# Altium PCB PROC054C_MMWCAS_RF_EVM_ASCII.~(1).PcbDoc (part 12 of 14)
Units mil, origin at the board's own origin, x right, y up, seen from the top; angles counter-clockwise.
Board outline 6299.21 x 5370.07 mil, 8 copper layers (L1 TOP, L2 GND, L3 SIGNAL 1, L4 GND, L5 SIGNAL 2, L6 SIGNAL 3, L7 GND, L8 BOTTOM), stack 53.5 mil thick; 775 components, 552 nets, 2648 pads, 7845 vias.
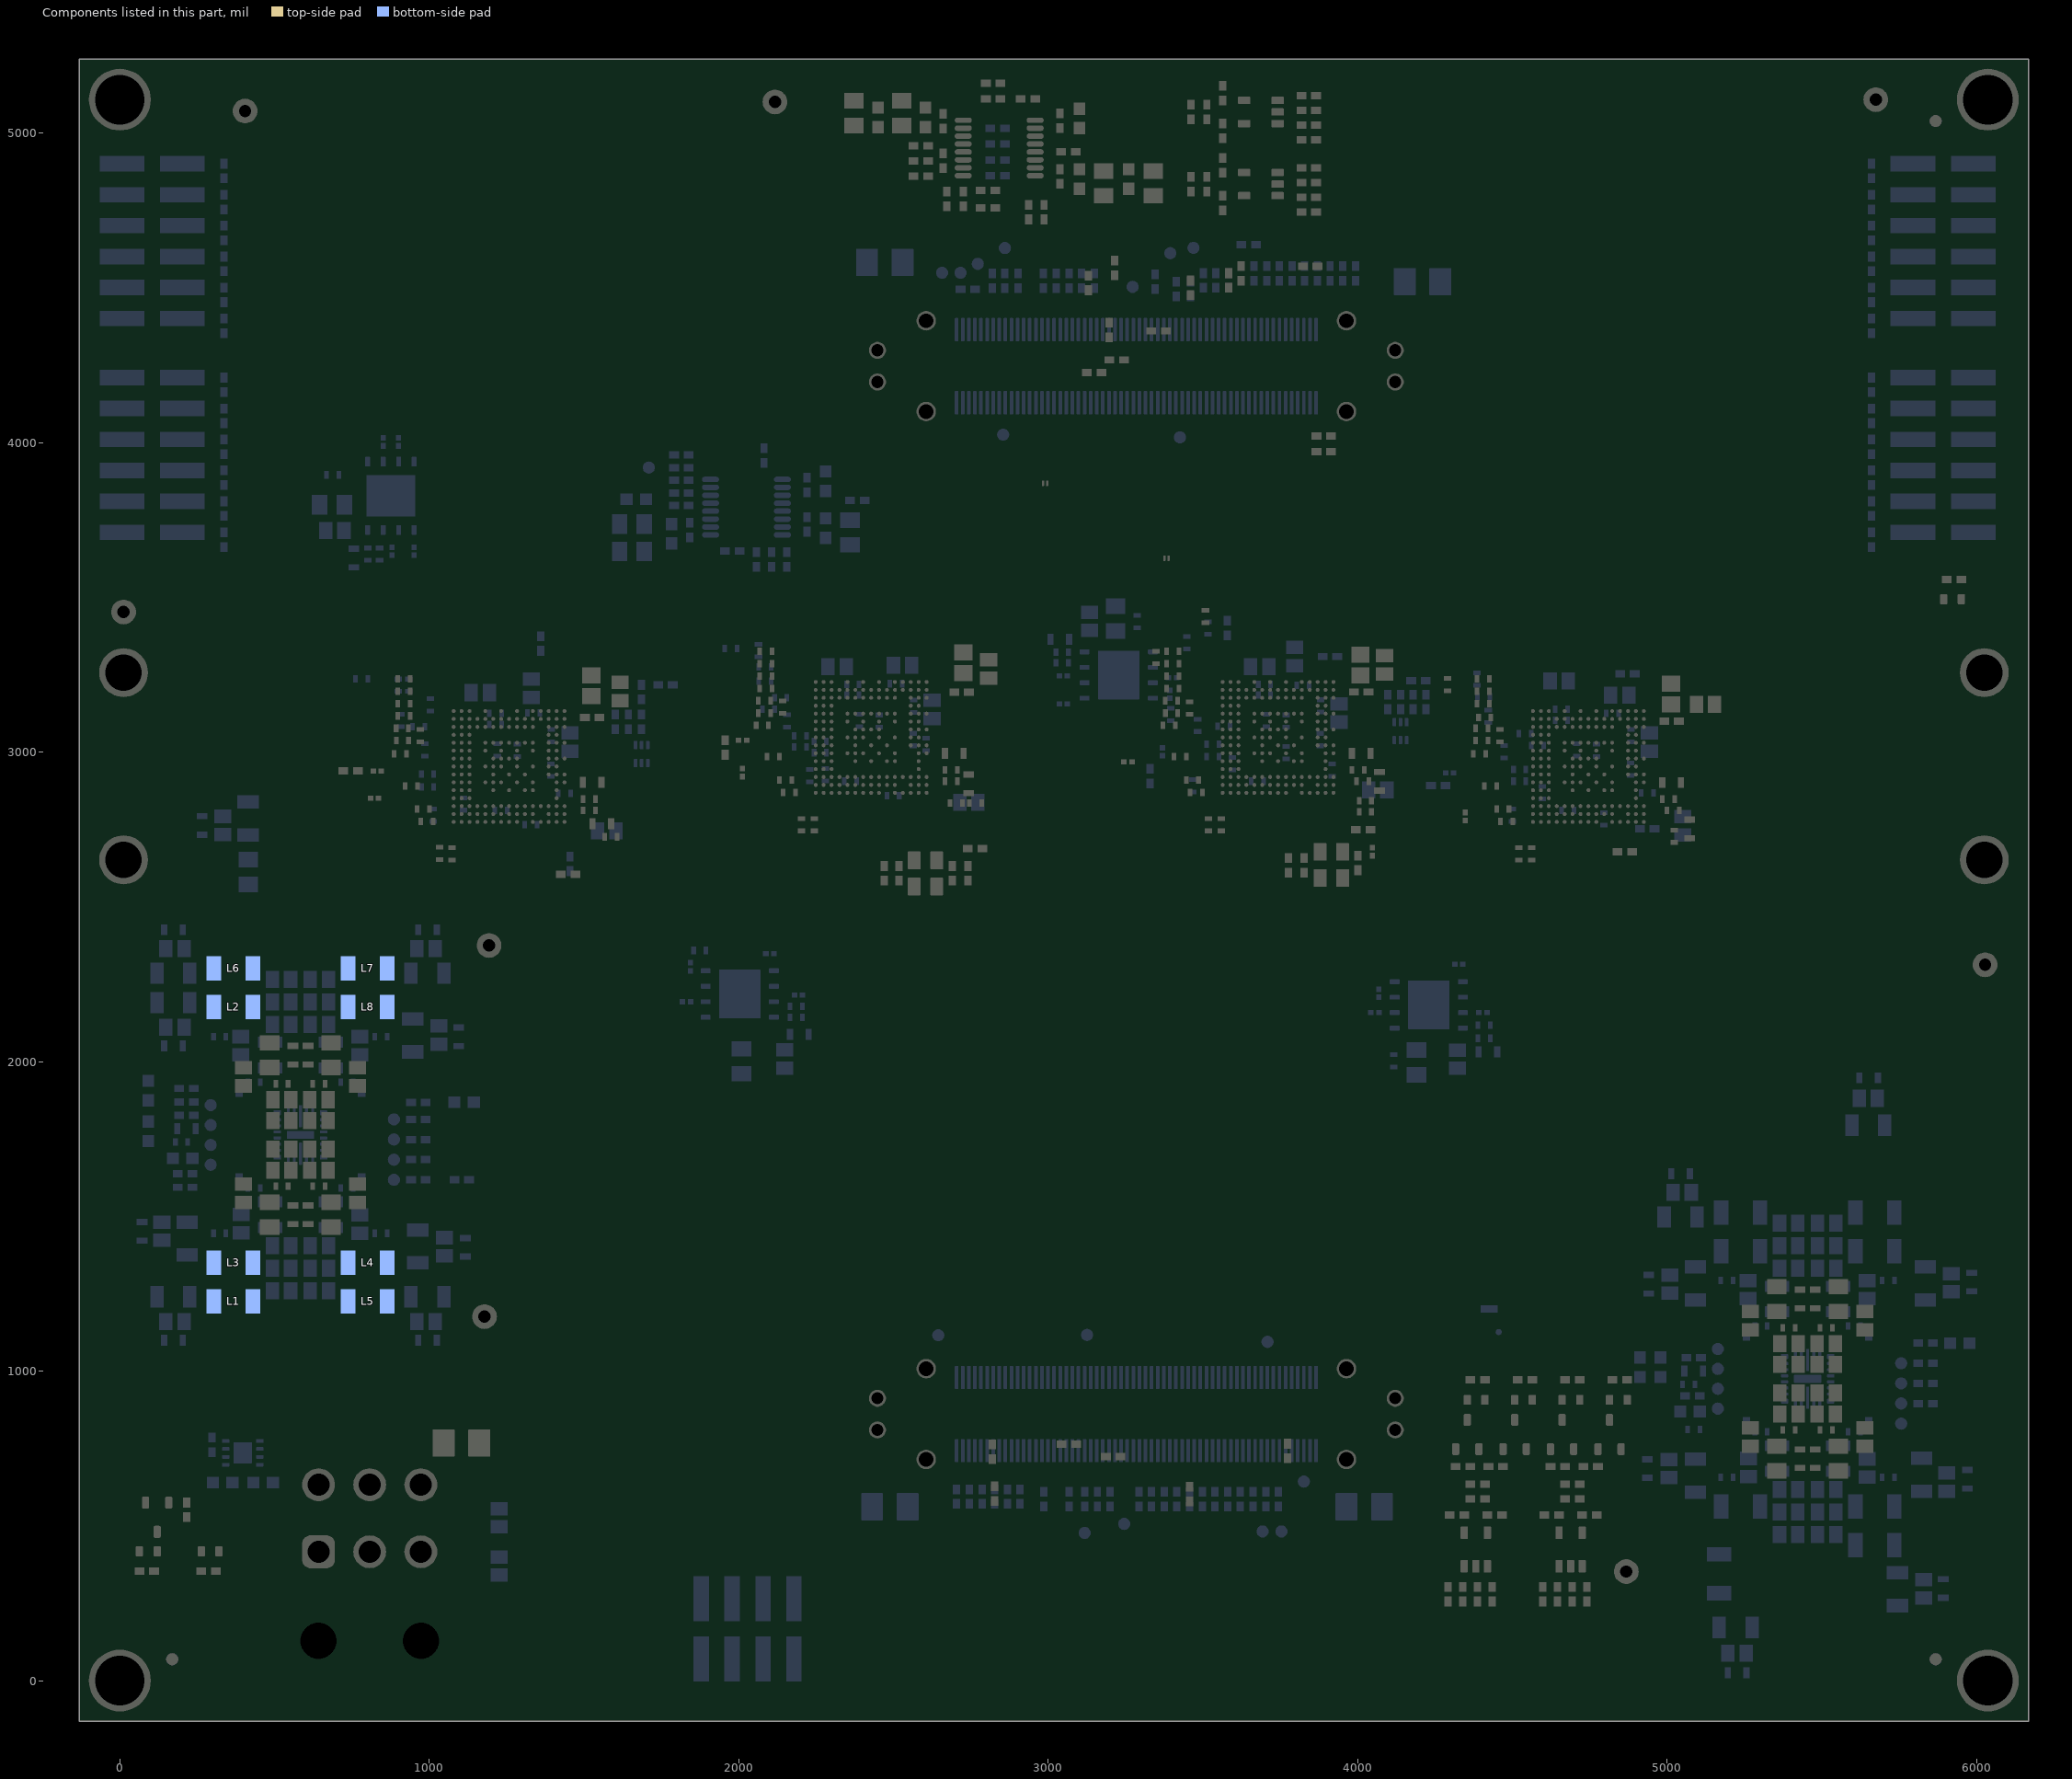
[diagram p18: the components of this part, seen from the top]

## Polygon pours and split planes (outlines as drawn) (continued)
GND on L8 BOTTOM "L8_BOTTOM_GND_P29719" (solid, remove dead copper, pour order 29719): 17 vertices, not listed, extent 731.81,1863.73 842.14,2042.6
GND on L8 BOTTOM "L8_BOTTOM_GND_P29760" (solid, remove dead copper, pour order 29760): 24 vertices, not listed, extent 530.59,1923.28 636.24,2303.75
12XX_4_1V0_RF1_FILT on L8 BOTTOM "L8_BOTTOM_12XX_4_1V0_RF1_FILT_P29792" (solid, remove dead copper, pour order 29792): 24 vertices, not listed, extent 479.15,2247.44 1317.72,3551.66
12XX_4_1V2_FILT on L8 BOTTOM "L8_BOTTOM_12XX_4_1V2_FILT_P29790" (solid, remove dead copper, pour order 29790): 19 vertices, not listed, extent -131.11,1296.94 332.13,3060.36
12XX_4_1V8_FILT on L8 BOTTOM "L8_BOTTOM_12XX_4_1V8_FILT_P29702" (solid, remove dead copper, pour order 29702): 1314.48,3068.75 1283.95,3099.27 1283.95,3185.88 1297.79,3199.72 1357.07,3199.72 1360.98,3195.82 1360.98,3156.42 1356.01,3151.45 1340.03,3151.45 1328.67,3140.09 1328.67,3082.94 1316.61,3070.88
12XX_3_1V8_FILT on L8 BOTTOM "L8_BOTTOM_12XX_3_1V8_FILT_P29703" (solid, remove dead copper, pour order 29703): 3799.3,3157.94 3799.3,3160.31 3764.59,3195.02 3764.59,3296.99 3768.63,3301.03 3817.76,3301.03 3824.31,3294.48 3824.31,3174.4 3808.57,3158.65
LMK2_3V3 on L8 BOTTOM "L8_BOTTOM_LMK2_3V3_P29704" (solid, remove dead copper, pour order 29704): 1985.94,3661.24 2019.56,3661.24 2021.37,3659.44 2021.37,3627.32 2032.47,3616.21 2066.39,3616.21 2070.9,3611.71 2070.9,3549.27 2068.19,3546.56 2002.15,3546.56 1982.34,3566.38 1982.34,3657.85 1985.51,3661.02
PMIC1_SW_B1 on L8 BOTTOM "L8_BOTTOM_PMIC1_SW_B1_P29708" (solid, remove dead copper, pour order 29708): 564.74,1621.53 540.48,1597.27 540.48,1534.8 531.2,1525.51 446.86,1525.51 441.43,1530.95 441.43,1600.06 444.98,1603.62 526.25,1603.62 564.74,1642.11
PMIC2_SW_B3 on L8 BOTTOM "L8_BOTTOM_PMIC2_SW_B3_P29711" (solid, remove dead copper, pour order 29711): 5435.47,1116.54 5411.21,1140.8 5411.21,1203.27 5401.92,1212.56 5317.59,1212.56 5312.15,1207.12 5312.15,1138 5315.71,1134.45 5396.98,1134.45 5435.47,1095.96
PMIC1_SW_B3 on L8 BOTTOM "L8_BOTTOM_PMIC1_SW_B3_P29709" (solid, remove dead copper, pour order 29709): 564.74,1904.39 540.48,1928.65 540.48,1991.13 531.2,2000.41 446.86,2000.41 441.43,1994.97 441.43,1925.86 444.98,1922.3 526.25,1922.3 564.74,1883.81
PMIC2_SW_B1 on L8 BOTTOM "L8_BOTTOM_PMIC2_SW_B1_P29707" (solid, remove dead copper, pour order 29707): 5435.47,833.68 5411.21,809.41 5411.21,746.94 5401.92,737.66 5317.59,737.66 5312.15,743.09 5312.15,812.21 5315.71,815.77 5396.98,815.77 5435.47,854.26
SYSTEM_3V3 on L8 BOTTOM "L8_BOTTOM_SYSTEM_3V3_P29713" (solid, remove dead copper, pour order 29713): 4119.08,1929.88 4150.24,1961.04 4150.24,1978.85 4161.13,1989.74 4225.69,1989.74 4230.89,1984.54 4230.89,1919.98 4211.1,1900.19 4127.03,1900.19 4119.08,1908.13
SYSTEM_3V3 on L8 BOTTOM "L8_BOTTOM_SYSTEM_3V3_P29714" (solid, remove dead copper, pour order 29714): 1655.67,3304.32 1655.67,3252.4 1673.06,3235.01 1673.06,3202.27 1676.13,3199.2 1751.58,3199.2 1757.72,3205.34 1757.72,3267.24 1716.4,3308.55 1659.81,3308.55 1655.72,3304.45
GND on L8 BOTTOM "L8_BOTTOM_GND_P29716" (solid, remove dead copper, pour order 29716): 2520.71,3233.05 2536.96,3249.29 2536.96,3308.95 2546.24,3318.24 2546.24,3337.25 2562.13,3353.13 2624.56,3353.13 2644,3333.69 2644,3286.65 2635.37,3278.02 2604.61,3278.02 2583.1,3256.51 2583.1,3235.11 2557,3209.01 2520.5,3209.01
12XX_1_1V0_RF2_FILT on L8 BOTTOM "L8_BOTTOM_12XX_1_1V0_RF2_FILT_P29722" (solid, remove dead copper, pour order 29722): 2575.22,3152.32 2566.3,3143.41 2518.78,3143.41 2509.79,3152.4 2509.79,3178.83 2528.38,3197.42 2565.14,3197.42 2593.02,3225.31 2593.02,3244.09 2611.23,3262.29 2666.34,3262.29 2672.43,3256.19 2672.43,3162.3 2662.35,3152.22
GND on L8 BOTTOM "L8_BOTTOM_GND_P29723" (solid, remove dead copper, pour order 29723): 19 vertices, not listed, extent 4830.85,3112.64 4957.73,3269.52
GND on L8 BOTTOM "L8_BOTTOM_GND_P29718" (solid, remove dead copper, pour order 29718): 17 vertices, not listed, extent 324.94,1863.73 435.27,2042.6
GND on L8 BOTTOM "L8_BOTTOM_GND_P29724" (solid, remove dead copper, pour order 29724): 55.37,1459.42 253.34,1459.39 262.11,1468.17 262.11,1516.41 251.59,1526.93 60.99,1526.93 51.3,1517.25 51.3,1463.49
GND on L8 BOTTOM "L8_BOTTOM_GND_P29726" (solid, remove dead copper, pour order 29726): 2310.48,3305.51 2310.48,3241.04 2325.47,3226.05 2341.84,3226.05 2350.84,3217.05 2350.84,3172.19 2241.17,3172.19 2214.62,3198.73 2214.62,3269.85 2259.77,3315 2300.99,3315
GND on L8 BOTTOM "L8_BOTTOM_GND_P29727" (solid, remove dead copper, pour order 29727): 1156.54,3219.67 1156.54,3162.35 1180.32,3138.57 1200.5,3138.57 1202.77,3136.3 1202.77,3076.8 1201.25,3075.29 1104.24,3075.29 1056.16,3123.38 1056.16,3167.32 1080.46,3191.62 1082.27,3191.62 1114.17,3223.53 1152.74,3223.53 1156.46,3219.81
GND on L8 BOTTOM "L8_BOTTOM_GND_P29728" (solid, remove dead copper, pour order 29728): 2743.43,2912.56 2743.43,2973.73 2774.02,3004.31 2793.61,3004.31 2827.53,2970.38 2827.53,2822.73 2808.42,2803.61 2753.95,2803.61 2743.42,2814.15 2743.42,2911.89
GND on L8 BOTTOM "L8_BOTTOM_GND_P29729" (solid, remove dead copper, pour order 29729): 5125.26,693.18 4922.11,693.06 4905.82,709.34 4905.82,748.12 4924.74,767.04 5112.73,767.04 5130.98,748.79 5130.98,698.9
GND on L8 BOTTOM "L8_BOTTOM_GND_P29730" (solid, remove dead copper, pour order 29730): 4049.36,427.21 4120.73,427.22 4132.64,439.13 4132.64,594.57 4120.07,607.14 4041.41,607.14 4036.71,602.44 4036.71,439.87
GND on L8 BOTTOM "L8_BOTTOM_GND_P29731" (solid, remove dead copper, pour order 29731): 2304.82,524.41 2304.82,603.47 2316.8,615.44 2463.57,615.44 2471.61,607.41 2471.61,519.68 2462.83,510.9 2318.33,510.9
GND on L8 BOTTOM "L8_BOTTOM_GND_P29733" (solid, remove dead copper, pour order 29733): 4644.68,3257.81 4644.68,3093.35 4639.57,3088.24 4553.73,3088.24 4533.76,3108.21 4533.95,3108.4 4533.95,3244.72 4557.27,3268.04 4634.41,3268.04 4644.52,3257.92
GND on L8 BOTTOM "L8_BOTTOM_GND_P29735" (solid, remove dead copper, pour order 29735): 5706.74,287.57 5904.93,287.65 5920.47,272.11 5920.47,228.75 5879.89,188.17 5714.78,188.17 5700.3,202.64 5700.3,281.13
QSPI_FLASH_3V3_3 on L8 BOTTOM "L8_BOTTOM_QSPI_FLASH_3V3_3_P29736" (solid, remove dead copper, pour order 29736): 17 vertices, not listed, extent 3053.43,3275.51 3300.68,3418.57
GND on L8 BOTTOM "L8_BOTTOM_GND_P29737" (solid, remove dead copper, pour order 29737): 251.93,2771.63 429.87,2771.53 457.14,2798.8 457.14,2867.2 450.2,2874.13 266.15,2874.13 239.05,2847.04 239.05,2784.52
GND on L8 BOTTOM "L8_BOTTOM_GND_P29738" (solid, remove dead copper, pour order 29738): 5234.36,197.62 5234.36,11.78 5254.9,-8.76 5315.01,-8.76 5336.05,12.28 5336.05,193.94 5320.82,209.17 5245.78,209.17 5234.47,197.86
GND on L8 BOTTOM "L8_BOTTOM_GND_P29740" (solid, remove dead copper, pour order 29740): 1136.85,1409.74 938.77,1409.74 917.18,1431.33 917.18,1495.24 932,1510.05 1113.99,1510.05 1147.98,1476.06 1147.98,1420.75 1137.01,1409.79
GND on L8 BOTTOM "L8_BOTTOM_GND_P29741" (solid, remove dead copper, pour order 29741): 4920.12,1273.11 5110.12,1273.11 5139.01,1244.22 5139.01,1186.07 5125.3,1172.37 4930.49,1172.37 4910.12,1192.74 4910.12,1263.22 4919.64,1272.74
GND on L8 BOTTOM "L8_BOTTOM_GND_P29742" (solid, remove dead copper, pour order 29742): 169.84,1088.49 169.83,1259.99 149.91,1279.91 67.74,1279.91 56.63,1268.79 56.63,1089.92 75.84,1070.71 152.06,1070.71
GND on L8 BOTTOM "L8_BOTTOM_GND_P29743" (solid, remove dead copper, pour order 29743): 997.21,1077.96 996.89,1266.04 1009.07,1278.22 1099.69,1278.22 1110.42,1267.28 1110.45,1076.9 1104.26,1070.71 1004.45,1070.71
GND on L8 BOTTOM "L8_BOTTOM_GND_P29744" (solid, remove dead copper, pour order 29744): 5040.56,1660.15 5040.56,1460.89 5036.7,1457.04 4930.05,1457.04 4927.35,1459.74 4927.35,1661.16 4933.54,1667.36 5033.35,1667.36
GND on L8 BOTTOM "L8_BOTTOM_GND_P29745" (solid, remove dead copper, pour order 29745): 997.84,2245.26 1005.7,2237.4 1102.59,2237.4 1110.45,2245.26 1110.45,2449.02 1104.26,2455.21 1004.45,2455.21 997.21,2447.97
12XX_1_1V8_FILT on L8 BOTTOM "L8_BOTTOM_12XX_1_1V8_FILT_P29746" (solid, remove dead copper, pour order 29746): 332.13,2222.83 332.13,2138.87 275.33,2082.08 275.33,2041.53 262.7,2028.89 196.29,2028.89 185.13,2040.06 185.13,2216.65 197.47,2228.99 326.01,2228.99 332.08,2222.91
GND on L8 BOTTOM "L8_BOTTOM_GND_P29747" (solid, remove dead copper, pour order 29747): 5643.31,1749.23 5643.31,1960.96 5621.7,1982.57 5556.19,1982.57 5536.6,1962.98 5536.6,1760.04 5555.51,1741.13 5635.11,1741.13 5642.94,1748.96
GND on L8 BOTTOM "L8_BOTTOM_GND_P29748" (solid, remove dead copper, pour order 29748): 907.32,1966.28 896.53,1977.07 896.53,2065.22 910.15,2078.84 1113.28,2078.2 1122.53,2068.95 1122.53,1974.86 1113.96,1966.28
LMK2_3V3 on L8 BOTTOM "L8_BOTTOM_LMK2_3V3_P29734" (solid, remove dead copper, pour order 29734): 2207.97,3730.27 2385.87,3730.27 2455.01,3661.14 2455.01,3649.75 2447.16,3641.91 2227.17,3641.91 2194.37,3674.71 2194.37,3717.72 2206.87,3730.22
12XX_4_1V8_FILT on L8 BOTTOM "L8_BOTTOM_12XX_4_1V8_FILT_P29749" (solid, remove dead copper, pour order 29749): 332.13,2341.49 311.01,2362.61 311.01,2403.27 266.74,2447.53 196.29,2447.53 185.13,2436.37 185.13,2259.78 197.47,2247.44 326.01,2247.44 332.08,2253.52
QSPI_FLASH_3V3_2 on L8 BOTTOM "L8_BOTTOM_QSPI_FLASH_3V3_2_P29739" (solid, remove dead copper, pour order 29739): 4108.15,2009.8 4095.5,2022.45 4095.51,2029.36 4128.41,2062.26 4270.24,2062.26 4329.98,2122 4361.68,2122 4372.82,2133.14 4400.06,2133.14 4403.51,2129.69 4403.51,2015.02 4398.28,2009.8
QSPI_FLASH_3V3_4 on L8 BOTTOM "L8_BOTTOM_QSPI_FLASH_3V3_4_P29750" (solid, remove dead copper, pour order 29750): 696.84,3909.9 704.45,3917.51 762.42,3917.51 774.97,3905.14 774.97,3769.35 813.86,3730.46 813.86,3705.83 852.74,3666.95 852.74,3652.82 841.38,3641.45 729.6,3641.45 696.84,3674.22
GND on L8 BOTTOM "L8_BOTTOM_GND_P29751" (solid, remove dead copper, pour order 29751): 5774.37,1277.94 6003.39,1278.01 6019.4,1261.99 6019.4,1196.69 5990.33,1167.61 5777,1167.61 5757.35,1187.26 5757.35,1260.92
SYSTEM_1V8 on L8 BOTTOM "L8_BOTTOM_SYSTEM_1V8_P29752" (solid, remove dead copper, pour order 29752): 447.57,2756.32 260.56,2756.58 244.13,2740.14 244.13,2676.83 312.92,2608.04 442.59,2608.04 452.18,2617.63 452.18,2751.71
QSPI_FLASH_3V3_1 on L8 BOTTOM "L8_BOTTOM_QSPI_FLASH_3V3_1_P29753" (solid, remove dead copper, pour order 29753): 1905.12,2085.04 1890.62,2070.54 1890.62,2024.38 1901.01,2013.47 2175.27,2013.47 2178.49,2016.69 2178.49,2185.59 2173.48,2190.6 2156.66,2190.6 2132.68,2166.63 2107.28,2166.63 2094.75,2154.1 2094.75,2119.75 2060.04,2085.04
12XX_1_1V2_FILT on L8 BOTTOM "L8_BOTTOM_12XX_1_1V2_FILT_P29754" (solid, remove dead copper, pour order 29754): 332.08,1272.41 332.17,1109.48 301.07,1078.39 196.29,1078.39 185.13,1089.56 185.13,1266.14 197.47,1278.48 326.01,1278.48
GND on L8 BOTTOM "L8_BOTTOM_GND_P29755" (solid, remove dead copper, pour order 29755): 5990.27,651.02 5799.61,650.95 5780.88,669.68 5780.88,783.52 5792.5,795.15 5952.19,795.15 5993.37,753.96 5993.37,654.12
GND on L8 BOTTOM "L8_BOTTOM_GND_P29756" (solid, remove dead copper, pour order 29756): 19 vertices, not listed, extent 2371.03,2979.69 2664.08,3136.04
GND on L8 BOTTOM "L8_BOTTOM_GND_P29758" (solid, remove dead copper, pour order 29758): 24 vertices, not listed, extent 5401.32,434.32 5506.97,814.79
GND on L8 BOTTOM "L8_BOTTOM_GND_P29759" (solid, remove dead copper, pour order 29759): 24 vertices, not listed, extent 5401.32,1135.43 5506.97,1515.89
GND on L8 BOTTOM "L8_BOTTOM_GND_P29761" (solid, remove dead copper, pour order 29761): 24 vertices, not listed, extent 530.59,1222.18 636.24,1602.64
12XX_1_1V0_RF1_FILT on L8 BOTTOM "L8_BOTTOM_12XX_1_1V0_RF1_FILT_P29762" (solid, remove dead copper, pour order 29762): 841.37,1393.48 1188.05,1393.48 1196.55,1384.98 1196.55,1304.55 1188.94,1296.94 841.07,1296.94 835,1303.01 834.95,1387.06
12XX_2_1V0_RF2_FILT on L8 BOTTOM "L8_BOTTOM_12XX_2_1V0_RF2_FILT_P29763" (solid, remove dead copper, pour order 29763): 5741.9,635.42 5985.12,635.42 5990.14,630.4 5990.14,534.13 5965.09,509.08 5711.8,509.08 5705.72,515.16 5705.67,515.24 5705.67,599.2
12XX_2_1V0_RF1_FILT on L8 BOTTOM "L8_BOTTOM_12XX_2_1V0_RF1_FILT_P29764" (solid, remove dead copper, pour order 29764): 5724.3,302.96 5900.66,302.96 5913.24,315.54 5913.24,417.72 5840.33,490.63 5711.8,490.63 5705.72,484.55 5705.63,321.63
12XX_3_1V8_FILT on L8 BOTTOM "L8_BOTTOM_12XX_3_1V8_FILT_P29765" (solid, remove dead copper, pour order 29765): 5129.82,1288.65 4927.22,1288.65 4916.02,1299.85 4916.02,1393.14 4950.21,1427.33 5186.95,1427.33 5197.81,1416.57 5197.81,1356.64
12XX_1_1V0_RF1_FILT on L8 BOTTOM "L8_BOTTOM_12XX_1_1V0_RF1_FILT_P29769" (solid, remove dead copper, pour order 29769): 22 vertices, not listed, extent 2212.61,3117.64 2472.16,3467.22
GND on L8 BOTTOM "L8_BOTTOM_GND_P29768" (solid, remove dead copper, pour order 29768): 18 vertices, not listed, extent 4635.94,2850.72 4978.96,3027.83
GND on L8 BOTTOM "L8_BOTTOM_GND_P29770" (solid, remove dead copper, pour order 29770): 169.87,2447.97 168.54,2026.3 159.29,2017.05 101.92,2017.05 56.63,2062.34 56.63,2403.84 108,2455.21 162.62,2455.21
PMIC2_12XX_23_1V8 on L8 BOTTOM "L8_BOTTOM_PMIC2_12XX_23_1V8_P29773" (solid, remove dead copper, pour order 29773): 5229.84,1539.43 5258.28,1567.87 5367.3,1567.87 5387.93,1546.73 5387.93,1297.59 5398.74,1286.78 5398.74,1259.08 5395.9,1256.24 5316.28,1256.23 5302.31,1270.2 5234.17,1270.2 5229.84,1274.53
PMIC2_12XX_2_1V0 on L8 BOTTOM "L8_BOTTOM_PMIC2_12XX_2_1V0_P29774" (solid, remove dead copper, pour order 29774): 5678.68,410.78 5650.25,382.34 5541.23,382.34 5520.59,403.48 5520.59,652.62 5509.78,663.43 5509.78,691.13 5512.62,693.97 5592.25,693.98 5606.22,680.01 5674.36,680.01 5678.68,675.69
PMIC2_12XX_3_1V0 on L8 BOTTOM "L8_BOTTOM_PMIC2_12XX_3_1V0_P29772" (solid, remove dead copper, pour order 29772): 5678.68,1539.43 5650.25,1567.87 5541.23,1567.87 5520.59,1546.73 5520.59,1297.59 5509.78,1286.78 5509.78,1259.08 5512.62,1256.24 5592.25,1256.23 5606.22,1270.2 5674.36,1270.2 5678.68,1274.53
PMIC1_12XX_4_1V0 on L8 BOTTOM "L8_BOTTOM_PMIC1_12XX_4_1V0_P29776" (solid, remove dead copper, pour order 29776): 807.96,2327.29 779.52,2355.73 670.5,2355.73 649.87,2334.59 649.87,2085.45 639.06,2074.63 639.06,2046.94 641.9,2044.1 721.52,2044.09 735.49,2058.06 803.63,2058.06 807.96,2062.38
PMIC1_12XX_1_1V0 on L8 BOTTOM "L8_BOTTOM_PMIC1_12XX_1_1V0_P29775" (solid, remove dead copper, pour order 29775): 807.96,1198.63 779.52,1170.2 670.5,1170.2 649.87,1191.34 649.87,1440.48 639.06,1451.29 639.06,1478.99 641.9,1481.83 721.52,1481.83 735.49,1467.86 803.63,1467.86 807.96,1463.54
PMIC1_12XX_14_1V2 on L8 BOTTOM "L8_BOTTOM_PMIC1_12XX_14_1V2_P29771" (solid, remove dead copper, pour order 29771): 359.12,1198.63 387.55,1170.2 496.57,1170.2 517.21,1191.34 517.21,1440.48 528.02,1451.29 528.02,1478.99 525.18,1481.83 445.55,1481.83 431.58,1467.86 363.44,1467.86 359.12,1463.54
PMIC2_12XX_23_1V2 on L8 BOTTOM "L8_BOTTOM_PMIC2_12XX_23_1V2_P29777" (solid, remove dead copper, pour order 29777): 17 vertices, not listed, extent 5111.94,382.34 5398.74,693.98
SYSTEM_5V0 on L8 BOTTOM "L8_BOTTOM_SYSTEM_5V0_P29779" (solid, remove dead copper, pour order 29779): 385.39,1155.02 781.54,1155.09 800.07,1136.57 800.07,1028.87 786.7,1015.5 384.6,1015.5 368.88,1031.23 368.88,1138.51
SYSTEM_5V0 on L8 BOTTOM "L8_BOTTOM_SYSTEM_5V0_P29780" (solid, remove dead copper, pour order 29780): 5256.11,1722.32 5652.26,1722.39 5670.79,1703.87 5670.79,1596.17 5657.43,1582.8 5255.33,1582.8 5239.6,1598.53 5239.6,1705.81
SYSTEM_5V0 on L8 BOTTOM "L8_BOTTOM_SYSTEM_5V0_P29778" (solid, remove dead copper, pour order 29778): 5256.11,367.16 5652.26,367.24 5670.79,348.71 5670.79,241.01 5657.43,227.65 5255.33,227.65 5239.6,243.37 5239.6,350.65
12XX_2_1V0_RF1_FILT on L8 BOTTOM "L8_BOTTOM_12XX_2_1V0_RF1_FILT_P29781" (solid, remove dead copper, pour order 29781): 4696.06,3074.55 4659.12,3111.49 4659.12,3260.66 4601.6,3318.18 4601.6,3490.74 4639.94,3529.09 4784.44,3529.09 4805.49,3508.04 4805.49,3411.24 4744.23,3349.98 4744.23,3058.09 4735.84,3049.7 4721.04,3049.7 4696.87,3073.87
PMIC1_12XX_14_1V8 on L8 BOTTOM "L8_BOTTOM_PMIC1_12XX_14_1V8_P29783" (solid, remove dead copper, pour order 29783): 18 vertices, not listed, extent 293.69,2044.09 528.02,2599.17
12XX_1_1V8_FILT on L8 BOTTOM "L8_BOTTOM_12XX_1_1V8_FILT_P29786" (solid, remove dead copper, pour order 29786): 2733.3,3018.37 2733.3,2986.35 2733.3,2693.85 2688.04,2648.59 2422.22,2648.59 2326.04,2744.77 2326.04,2941.5 2353.94,2968.94 2544.94,2968.94 2594.37,3018.37
12XX_1_1V8_FILT on L8 BOTTOM "L8_BOTTOM_12XX_1_1V8_FILT_P29732" (solid, remove dead copper, pour order 29732): 2457.74,3437.82 2466.79,3446.87 2539.89,3446.87 2548.77,3437.81 2548.77,3407.34 2530.87,3389.44 2530.87,3330.91 2521.89,3321.94 2521.89,3255.09 2505.24,3238.43 2505.24,3190.24 2488.85,3173.85 2457.74,3204.97
12XX_2_1V2_FILT on L8 BOTTOM "L8_BOTTOM_12XX_2_1V2_FILT_P29787" (solid, remove dead copper, pour order 29787): 23 vertices, not listed, extent 4545.61,495.57 5202.85,1325.64
SYSTEM_5V0 on L8 BOTTOM "L8_BOTTOM_SYSTEM_5V0_P29791" (solid, remove dead copper, pour order 29791): 24 vertices, not listed, extent 2487.38,46.76 4021.69,783.63
GND on L8 BOTTOM "L8_BOTTOM_GND_P29767" (solid, remove dead copper, pour order 29767): 18 vertices, not listed, extent 1184.59,2879.45 1492.81,3042.1
GND on L8 BOTTOM "L8_BOTTOM_GND_P29766" (solid, remove dead copper, pour order 29766): 3649.25,3104.96 3649.25,3049.61 3702.98,2995.88 3911.78,2995.88 3977.42,3061.52 3977.42,3110.01 3968.87,3118.56 3662.85,3118.56
SYSTEM_3V3 on L8 BOTTOM "L8_BOTTOM_SYSTEM_3V3_P29715" (solid, remove dead copper, pour order 29715): 312.14,611.67 223.07,611.67 209.27,625.47 209.27,683.1 227.78,701.61 236.86,701.61 353.82,701.61 353.89,692 342.2,680.32 331.61,680.32 321.28,669.99 321.28,620.81
GND on L8 BOTTOM "L8_BOTTOM_GND_P29717" (solid, remove dead copper, pour order 29717): 377.44,716.09 369.17,707.82 369.17,684.67 342.1,657.59 342.1,594.18 355.44,580.84 437.95,580.84 452.35,595.24 452.35,658.52 424.84,686.04 424.84,708.06 416.81,716.09
12XX_3_1V2_FILT on L8 BOTTOM "L8_BOTTOM_12XX_3_1V2_FILT_P29784" (solid, remove dead copper, pour order 29784): 3415,2926.83 3522.31,3034.14 3632.94,3034.14 3688.8,2978.27 3796.08,2978.27 3816.09,2958.26 3816.09,2796.64 3710.44,2690.99 3475.55,2690.99 3415,2751.55
SYSTEM_5V0 on L8 BOTTOM "L8_BOTTOM_SYSTEM_5V0_P29757" (solid, remove dead copper, pour order 29757): 18 vertices, not listed, extent 440.48,612.88 715.24,828.57
SYSTEM_3V3 on L3 SIGNAL 1 "L3_SIGNAL_1_SYSTEM_3V3_P29682" (solid, remove dead copper, pour order 29682): 19 vertices, not listed, extent 2819,3443.85 6168.77,5235.17
12XX_3_1V2_FILT on L3 SIGNAL 1 "L3_SIGNAL_1_12XX_3_1V2_FILT_P29678" (solid, remove dead copper, pour order 29678): 4005.77,1049.26 3933.6,977.08 3443.92,977.08 3238.07,1181.62 3238.07,1884.53 3238.07,2920.34 3282.12,2964.39 3458.65,3140.84 3651.28,3140.84 3798.48,2993.64 3798.48,1309.59 4005.77,1102.29
SYSTEM_3V3 on L3 SIGNAL 1 "L3_SIGNAL_1_SYSTEM_3V3_P29675" (solid, remove dead copper, pour order 29675): 4243.58,239.65 5079.35,239.61 5228.42,388.68 5993.24,388.68 6020.97,416.42 6020.97,978.39 6000.72,998.64 5897.16,998.64 5883.55,985.03 5883.55,761.72 5790.91,669.08 4284.49,669.08 4216.52,601.11 4216.52,266.71
12XX_1_1V8_FILT on L3 SIGNAL 1 "L3_SIGNAL_1_12XX_1_1V8_FILT_P29677" (solid, remove dead copper, pour order 29677): 33 vertices, not listed, extent 219.24,2018.28 2602.93,3521.26
12XX_4_1V8_FILT on L3 SIGNAL 1 "L3_SIGNAL_1_12XX_4_1V8_FILT_P29674" (solid, remove dead copper, pour order 29674): 33 vertices, not listed, extent 229.3,2334.58 1604.42,3118.67
SYSTEM_1V8 on L3 SIGNAL 1 "L3_SIGNAL_1_SYSTEM_1V8_P29681" (solid, remove dead copper, pour order 29681): 3338.64,4707.22 2888.04,4707.22 2887.04,4706.22 1925.24,4706.22 646.35,4706.22 644.69,4707.22 621.9,4730 621.9,4890.17 965.5,5233.76 3248.9,5233.76 3382.4,5100.27 3382.4,4750.97
12XX_2_1V2_FILT on L3 SIGNAL 1 "L3_SIGNAL_1_12XX_2_1V2_FILT_P29680" (solid, remove dead copper, pour order 29680): 4194.59,1669.78 4639.62,1224.75 4833.81,1224.75 4948.3,1338.9 4948.3,3000.29 4739.1,3209.49 4264.45,3209.49 4194.59,3139.64
12XX_4_1V2_FILT on L3 SIGNAL 1 "L3_SIGNAL_1_12XX_4_1V2_FILT_P29679" (solid, remove dead copper, pour order 29679): 26 vertices, not listed, extent -127.34,1294.53 1171.02,3439.25
12XX_1_1V0_RF2_FILT on L3 SIGNAL 1 "L3_SIGNAL_1_12XX_1_1V0_RF2_FILT_P29676" (solid, remove dead copper, pour order 29676): 1503.23,627.05 1464.92,665.36 1464.92,753.57 2246.94,1535.59 2757.85,1535.59 2822.27,1471.17 2822.27,709.1 2740.22,627.05
PMIC2_3V3 on L3 SIGNAL 1 "L3_SIGNAL_1_PMIC2_3V3_P29673" (solid, remove dead copper, pour order 29673): 19 vertices, not listed, extent 4858.79,683.99 5874.61,1146.4
12XX_1_1V2_FILT on L3 SIGNAL 1 "L3_SIGNAL_1_12XX_1_1V2_FILT_P29683" (solid, remove dead copper, pour order 29683): 38 vertices, not listed, extent -132.18,237.72 2611.83,3138.94
no net on Top Solder "Top Solder-No Net" (solid, pour order 29799): 3332.36,3390.31 3432.91,3390.31 3432.91,3495.97 3446.81,3509.87 3446.81,3605.94 3491.24,3650.37 3530.36,3650.37 3530.36,3735.15 3233.36,3735.15 3233.36,3648.77 3275.61,3648.77 3316.33,3608.05 3316.33,3520.34 3332.36,3504.31 3332.36,3390.31
no net on Top Solder "Top Solder-No Net" (solid, pour order 29801): 67 vertices, not listed, extent 3614,3123.04 5771.11,5188
no net on Top Solder "Top Solder-No Net" (solid, pour order 29803): 146 vertices, not listed, extent 1312.4,1032 5351,3172.49
GND on Top Solder "Top Solder-No Net" (solid, pour order 29802): 66 vertices, not listed, extent 600,3123.04 2718,5188
no net on Top Solder "Top Solder-No Net" (solid, pour order 29800): 2940,3623.5 3040.55,3623.5 3040.55,3737.98 3054.45,3751.88 3054.45,3847.95 3098.88,3892.38 3138,3892.38 3138,3977.16 2841,3977.16 2841,3890.78 2883.25,3890.78 2923.97,3850.06 2923.97,3762.35 2940,3746.32 2940,3623.5
12XX_1_1V0_RF1_FILT on L5 SIGNAL 2 "L5_SIGNAL_2_12XX_1_1V0_RF1_FILT_P29689" (solid, remove dead copper, pour order 29689): 27 vertices, not listed, extent 1117.03,1258.71 2672.13,3484.42
GND on L5 SIGNAL 2 "L5_SIGNAL_2_GND_P29692" (solid, remove dead copper, pour order 29692): -131,-131 6168.21,-131 6168.21,5239.07 -131,5239.07
SYSTEM_3V3 on L5 SIGNAL 2 "L5_SIGNAL_2_SYSTEM_3V3_P29691" (solid, remove dead copper, pour order 29691): 188 vertices, not listed, extent -131,-131 5930.08,5238.71
12XX_2_1V0_RF2_FILT on L5 SIGNAL 2 "L5_SIGNAL_2_12XX_2_1V0_RF2_FILT_P29688" (solid, remove dead copper, pour order 29688): 17 vertices, not listed, extent 5222.4,486.7 6164.28,2979.58
12XX_3_1V8_FILT on L5 SIGNAL 2 "L5_SIGNAL_2_12XX_3_1V8_FILT_P29690" (solid, remove dead copper, pour order 29690): 23 vertices, not listed, extent 3471.79,1035.43 5014.03,3258.13
12XX_2_1V0_RF1_FILT on L5 SIGNAL 2 "L5_SIGNAL_2_12XX_2_1V0_RF1_FILT_P29687" (solid, remove dead copper, pour order 29687): 5207.33,2501.24 5207.33,2455.45 5594.88,2067.91 5594.88,1991.57 5521.99,1918.68 4789.47,1918.68 4688.92,2017.98 4688.92,2235.08 4688.92,3512.52 4715.23,3538.84 4780.41,3538.84 5207.33,3111.92 5207.33,2592.86
SYSTEM_3V3 on L5 SIGNAL 2 "L5_SIGNAL_2_SYSTEM_3V3_P29686" (solid, remove dead copper, pour order 29686): 48 vertices, not listed, extent 3003,2913.21 4375.6,4618.88
12XX_4_1V8_FILT on L5 SIGNAL 2 "L5_SIGNAL_2_12XX_4_1V8_FILT_P29685" (solid, remove dead copper, pour order 29685): 1483.42,2743.92 1516.67,2777.17 1516.67,2997.47 1407.92,3107.62 1406.07,3109.48 1405.21,3108.63 1123.12,3108.63 1084.91,3070.42 1084.91,2812.77 1153.77,2743.92
12XX_3_1V2_FILT on L6 SIGNAL 3 "L6_SIGNAL_3_12XX_3_1V2_FILT_P29697" (solid, remove dead copper, pour order 29697): 3456.69,3146.71 3456.69,2997.69 3415,2956 3415,2747.99 3486.3,2676.69 3796.7,2676.69 3844,2723.99 3844,3024.66 3718.66,3150 3487,3150
SYSTEM_1V8 on L6 SIGNAL 3 "L6_SIGNAL_3_SYSTEM_1V8_P29699" (solid, remove dead copper, pour order 29699): 699.62,4851.17 740.01,4810.77 740.01,4218.05 394.02,3872.06 394.02,2608.2 356.97,2571.15 -112.55,2571.15 -122.82,2581.41 -122.82,4126.55 601.8,4851.17
12XX_1_1V0_RF2_FILT on L6 SIGNAL 3 "L6_SIGNAL_3_12XX_1_1V0_RF2_FILT_P29698" (solid, remove dead copper, pour order 29698): 2579.23,2950.74 2448.05,2819.56 2448.05,2474.21 2746.53,2175.12 2746.53,1290.34 2775.41,1261.46 3040.55,1261.46 3093.57,1314.48 3093.57,2473.6 2846.3,2720.87 2846.3,3219.22 2797.24,3268.28 2620.87,3268.28 2579.23,3226.64
12XX_1_1V8_FILT on L6 SIGNAL 3 "L6_SIGNAL_3_12XX_1_1V8_FILT_P29695" (solid, remove dead copper, pour order 29695): 2360.09,3200.58 2360.09,3385.41 2414.88,3440.21 2556.75,3440.21 2583,3413.95 2583,3260.01 2562.24,3239.25 2562.24,2955.31 2506.78,2899.85 2352.31,2899.85 2320.99,2931.17 2320.99,3161.49
12XX_4_1V8_FILT on L6 SIGNAL 3 "L6_SIGNAL_3_12XX_4_1V8_FILT_P29693" (solid, remove dead copper, pour order 29693): 1150.99,3079.99 1219.62,3148.62 1349.56,3148.62 1409.71,3088.46 1409.71,2833.69 1394,2817.98 1185.56,2817.98 1150.99,2852.55
12XX_2_1V2_FILT on L6 SIGNAL 3 "L6_SIGNAL_3_12XX_2_1V2_FILT_P29694" (solid, remove dead copper, pour order 29694): 4660.57,2646 4690.73,2676.15 4690.73,2945.36 4562.97,3073.12 4446.88,3073.12 4423.38,3049.63 4423.38,2688.31 4465.69,2646
12XX_2_1V8_FILT on L6 SIGNAL 3 "L6_SIGNAL_3_12XX_2_1V8_FILT_P29696" (solid, remove dead copper, pour order 29696): 4684.4,2807.14 4684.4,2862.48 4671.94,2874.94 4671.94,3022.89 4643.09,3051.75 4643.09,3107.75 4713.9,3178.56 4946.18,3178.56 5038.95,3085.78 5038.95,2787.87 4975.87,2724.79 4766.75,2724.79
SYSTEM_5V0 on L6 SIGNAL 3 "L6_SIGNAL_3_SYSTEM_5V0_P29700" (solid, remove dead copper, pour order 29700): 49 vertices, not listed, extent -129.36,-130.66 6168.33,5239.22
GND on L2 GND "L2_GND_GND_P29672" (solid, remove dead copper, pour order 29672): -131,-131 6168.21,-131 6168.21,5239.07 -131,5239.07
GND on L4 GND "L4_GND_GND_P29684" (solid, remove dead copper, pour order 29684): -131,-131 6168.21,-131 6168.21,5239.07 -131,5239.07
GND on L7 GND "L7_GND_GND_P29701" (solid, remove dead copper, pour order 29701): -131,-131 6168.21,-131 6168.21,5239.07 -131,5239.07

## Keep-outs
L2 GND:
  circle w1: c4899.43,2953.5 r6.17
  circle w1: c4899.44,3004.68 r6.17
  circle w1: c4899.43,3055.86 r6.17
  circle w1: c4797.07,3107.04 r6.17
  circle w1: c4745.89,3107.04 r6.17
  circle w1: c4694.71,3107.04 r6.17
  circle w1: c4643.53,3107.04 r6.17
  circle w1: c3896.43,3047.5 r6.17
  circle w1: c3896.43,3098.68 r6.17
  circle w1: c3896.43,3149.86 r6.17
  circle w1: c3794.07,3201.04 r6.17
  circle w1: c3742.89,3201.04 r6.17
  circle w1: c3691.71,3201.04 r6.17
  circle w1: c3640.53,3201.04 r6.17
  circle w1: c2581.43,3047.5 r6.17
  circle w1: c2581.43,3098.68 r6.17
  circle w1: c2581.43,3149.86 r6.17
  circle w1: c2479.07,3201.04 r6.17
  circle w1: c2427.89,3201.04 r6.17
  circle w1: c2376.71,3201.04 r6.17
  circle w1: c2325.53,3201.04 r6.17
  circle w1: c1411.43,2953.5 r6.17
  circle w1: c1411.43,3004.68 r6.17
  circle w1: c1411.43,3055.86 r6.17
  circle w1: c1309.07,3107.04 r6.17
  circle w1: c1257.89,3107.04 r6.17
  circle w1: c1206.71,3107.04 r6.17
  circle w1: c1155.53,3107.04 r6.17
  circle w1: c1411.43,3236 r18.5
  circle w1: c2583,3374.01 r18.5
  circle w1: c3896.43,3374 r18.5
L4 GND:
  circle w1: c2583,3374.01 r18.5
  circle w1: c1411.43,3236 r18.5
  circle w1: c3896.43,3374 r18.5
L5 SIGNAL 2:
  circle w1: c2583,3374.01 r18.5
  circle w1: c1411.43,3236 r18.5
  circle w1: c3896.43,3374 r18.5
L6 SIGNAL 3:
  circle w1: c2583,3374.01 r18.5
L7 GND:
  circle w1: c2583,3374.01 r18.5
  circle w1: c1411.43,3236 r18.5
  circle w1: c3896.43,3374 r18.5
L8 BOTTOM:
  circle w1: c2583,3374.01 r18.5
  circle w1: c1411.43,3236 r18.5
  circle w1: c3896.43,3374 r18.5
Keep-Out Layer:
  circle w1: c0,5108 r110
  circle w1: c0,0 r110
  circle w1: c6037,0 r110
  circle w1: c6037,5108 r110
  circle w1: c12,3257 r90
  circle w1: c12,2652 r90
  circle w1: c642.01,128.84 r90
  circle w1: c972.72,128.84 r90
  circle w1: c6025.21,3257 r90
  circle w1: c6025.21,2652 r90
  lines w10: -136,-131 ccw(c-131,-131) -131,-136 6168.21,-136 ccw(c6168.21,-131) 6173.21,-131 6173.21,5239.07 ccw(c6168.21,5239.07) 6168.21,5244.07 -131,5244.07 ccw(c-131,5239.07) -136,5239.07 -136,-131
  text ".Layer_Name" at 446,-989.49 h60

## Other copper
L1 TOP:
  drawing of 102 lines, arcs and shapes, not listed
  text "1" at 1257.24,7.47 h65
  text ".Layer_Name" at 446,-989.49 h60
L2 GND:
  region net 12XX_1_1V0_RF2_FILT: 2620.92,3259.25 2665.33,3259.25 2670.56,3254.02 2670.56,3226.92 2665.38,3221.74 2638.48,3221.74 2633.14,3227.07 2633.14,3239.54 2631.24,3241.45 2618.47,3241.45 2613.33,3246.59 2613.33,3251.44
  region net SYSTEM_5V0: 2515.39,514.41 2579.92,514.41 2585.03,509.31 2585.03,461.62 2579.6,456.18 2512.89,456.18 2507.35,461.73 2507.35,508.77 2513,514.41 2515.32,514.41
  region net 12XX_1_1V8_FILT: 2509.9,3360.96 2509.9,3384.51 2515.63,3390.24 2515.63,3402.55 2526.45,3413.37 2526.45,3418.78 2532.18,3424.51 2537.8,3424.51 2543.21,3419.1 2543.21,3410.19 2535.36,3402.34 2535.36,3398.41 2526.77,3389.82 2526.77,3375.28 2525.18,3373.69 2525.18,3361.59 2519.87,3356.29
  region net 12XX_1_1V0_RF1_FILT: 2242.48,3438.84 2253.42,3427.91 2253.42,3403.17 2258.55,3398.04 2285.85,3398.04 2291.36,3403.54 2291.36,3430.62 2286.08,3435.9 2264.2,3435.9 2260.58,3439.52 2260.58,3446.84 2255.3,3452.12 2247.64,3452.12 2242.48,3446.96
  region net SYSTEM_3V3: 4845.85,289.56 4894.85,289.56 4900.29,284.12 4900.29,255.7 4894.37,249.77 4846.56,249.77 4840.64,255.7 4840.64,284.36 4845.84,289.55
  region net 12XX_1_1V0_RF1_FILT: 1146.34,1308.09 1152.4,1302.04 1179.47,1302.04 1186.13,1308.64 1186.13,1374.29 1180.2,1380.21 1151.78,1380.21 1146.34,1374.77
  region net 12XX_1_1V2_FILT: 250.75,1173.19 244.84,1167.28 244.84,1120.13 251.44,1113.54 296.41,1113.54 303.01,1120.13 303.01,1166.96 296.78,1173.19
  region net 12XX_4_1V2_FILT: 158.43,1351.31 164.02,1356.9 164.02,1385.06 157.98,1391.1 72,1391.1 66.08,1385.18 66.08,1356.76 71.53,1351.31
  region net 12XX_1_1V8_FILT: 234.22,2041.49 239.81,2035.9 267.97,2035.9 274.01,2041.94 274.01,2127.92 268.09,2133.84 239.67,2133.84 234.22,2128.39
  region net 12XX_4_1V8_FILT: 250.75,2411.83 244.84,2405.92 244.84,2358.78 251.44,2352.18 296.41,2352.18 303.01,2358.78 303.01,2405.6 296.78,2411.83
  region net SYSTEM_1V8: 307.86,2641.07 307.86,2690.07 313.3,2695.51 341.72,2695.51 347.65,2689.59 347.65,2641.78 341.72,2635.86 313.06,2635.86 307.87,2641.06
  region net 12XX_4_1V2_FILT: -21.09,2941.66 -15.5,2936.08 12.66,2936.08 18.7,2942.12 18.7,3028.09 12.78,3034.02 -15.64,3034.02 -21.09,3028.57
  region net SYSTEM_1V8: 662.48,4740.5 662.48,4789.5 667.93,4794.94 696.35,4794.94 702.27,4789.02 702.27,4741.22 696.35,4735.29 667.69,4735.29 662.49,4740.49
  region net GND: 2389.91,4689.37 2384.62,4684.08 2384.9,4683.8 2384.9,4635.9 2391.08,4629.72 2437.22,4629.72 2443.65,4636.15 2443.65,4684.1 2438.39,4689.37
  region net SYSTEM_5V0: 2503.12,4689.87 2497.84,4684.58 2498.12,4684.3 2498.12,4636.39 2504.3,4630.22 2550.43,4630.22 2556.87,4636.65 2556.87,4684.6 2551.6,4689.87
  region net SYSTEM_5V0: 4128.16,4421 4122.87,4415.71 4123.16,4415.43 4123.16,4367.52 4129.33,4361.35 4175.47,4361.35 4181.9,4367.78 4181.9,4415.73 4176.64,4421
  region net SYSTEM_3V3: 5428.5,5134.79 5423.08,5140.21 5375.13,5140.21 5369.76,5134.91 5369.76,5105.96 5375.02,5100.7 5423.5,5100.7 5428.78,5105.99 5428.5,5106.27
  region net 12XX_2_1V0_RF1_FILT: 4785.96,3522.44 4780.54,3527.86 4732.59,3527.86 4727.22,3522.56 4727.22,3493.62 4732.48,3488.36 4780.96,3488.36 4786.25,3493.64 4785.96,3493.93
  region net 12XX_2_1V0_RF2_FILT: 5238.93,2890.61 5244.61,2884.92 5272.41,2884.92 5278.44,2890.95 5278.44,2957.75 5273.13,2963.12 5244.19,2963.12 5238.93,2957.86
  region net 12XX_2_1V0_RF1_FILT: 5530.8,2067.9 5525.52,2062.62 5525.8,2062.33 5525.8,2014.43 5531.98,2008.25 5578.11,2008.25 5584.55,2014.69 5584.55,2062.64 5579.28,2067.9
  region net PMIC2_VIN_B3: 5338.43,1070.07 5333.25,1064.89 5287.55,1064.89 5282.54,1069.9 5282.54,1078.84 5324.94,1121.23 5332.95,1121.23 5338.43,1115.76
  region net PMIC2_VIN_B2: 5570.1,1070.07 5575.28,1064.89 5620.98,1064.89 5625.98,1069.9 5625.98,1078.84 5583.59,1121.23 5575.57,1121.23 5570.1,1115.76
  region net PMIC2_VIN_B0: 5570.1,880.14 5575.28,885.32 5620.98,885.32 5625.98,880.31 5625.98,871.38 5583.59,828.98 5575.57,828.98 5570.1,834.46
  region net PMIC2_VIN_B1: 5338.43,880.14 5333.25,885.32 5287.55,885.32 5282.54,880.31 5282.54,871.38 5324.94,828.98 5332.95,828.98 5338.43,834.46
  region net PMIC1_VIN_B1: 467.7,1668 462.53,1673.18 416.83,1673.18 411.82,1668.17 411.82,1659.23 454.22,1616.84 462.23,1616.84 467.7,1622.31
  region net PMIC1_VIN_B0: 699.37,1668 704.55,1673.18 750.25,1673.18 755.26,1668.17 755.26,1659.23 712.86,1616.84 704.85,1616.84 699.37,1622.31
  region net PMIC1_VIN_B2: 699.37,1857.93 704.55,1852.75 750.25,1852.75 755.26,1857.75 755.26,1866.69 712.86,1909.09 704.85,1909.09 699.37,1903.61
  region net PMIC1_VIN_B3: 467.7,1857.93 462.53,1852.75 416.83,1852.75 411.82,1857.75 411.82,1866.69 454.22,1909.09 462.23,1909.09 467.7,1903.61
  region net 12XX_2_1V0_RF1_FILT: 5805.08,436.36 5799.8,431.08 5800.08,430.8 5800.08,382.89 5806.26,376.72 5852.39,376.72 5858.82,383.15 5858.82,431.1 5853.56,436.36
  region net 12XX_2_1V0_RF2_FILT: 5774.35,579.38 5769.06,574.1 5769.34,573.81 5769.34,525.91 5775.52,519.73 5821.66,519.73 5828.09,526.16 5828.09,574.12 5822.82,579.38
  region net 12XX_1_1V0_RF2_FILT: 2761.15,1302.47 2761.15,1284.2 2767.54,1277.81 2794.49,1277.81 2800.93,1284.25 2800.93,1351 2795.01,1356.92 2766.59,1356.92 2761.14,1351.48 2761.14,1302.48
  region net 12XX_2_1V2_FILT: 4755.72,1315.7 4750.43,1310.42 4750.71,1310.13 4750.71,1262.23 4756.89,1256.05 4803.03,1256.05 4809.46,1262.48 4809.46,1310.44 4804.19,1315.7
  region net 12XX_3_1V8_FILT: 4929.6,1404.03 4924.32,1398.74 4924.6,1398.46 4924.6,1350.56 4930.78,1344.38 4976.91,1344.38 4983.34,1350.81 4983.34,1398.77 4978.08,1404.03
  region net SYSTEM_5V0: 3939.25,650.91 3988.25,650.91 3993.69,645.46 3993.69,617.04 3987.77,611.12 3939.96,611.12 3934.04,617.04 3934.04,645.7 3939.24,650.9
  region net SYSTEM_5V0: 3938.79,510.36 3987.79,510.36 3993.24,504.92 3993.24,476.5 3987.32,470.57 3939.51,470.57 3933.59,476.5 3933.59,505.16 3938.79,510.35
  region net GND: 4119.13,512.68 4123.93,507.89 4123.93,437.77 4118.78,432.62 4050.85,432.62 4043.44,440.03 4043.44,505.72 4050.4,512.68
  region net 12XX_3_1V2_FILT: 3927.84,1110.58 3933.19,1115.94 3982.82,1115.94 3987.48,1111.28 3987.48,1062.72 3981.35,1056.58 3934.18,1056.58 3927.84,1062.92
  region net SYSTEM_3V3: 215.58,674.66 215.58,627.6 222.37,620.82 269.86,620.82 274.57,625.52 274.57,676.3 270.08,680.79 221.71,680.79
  region net 12XX_1_1V0_RF2_FILT: 1496.65,721.57 1496.65,676.41 1497.73,675.32 1504.94,668.12 1552.12,668.12 1558.09,674.09 1558.09,723.96 1553.52,728.53 1503.61,728.53
  region net GND: 2525.94,3438.17 2525.69,3432.67 2519.11,3425.7 2513.62,3428.49 2513.69,3433.68
  pour cut-out: 1317.77,2696.74 1317.77,2690.42 1329.87,2690.53 1329.87,2711.78 1324,2711.78
  pour cut-out: 2192.66,2682.81 2186.34,2682.81 2186.45,2670.7 2207.7,2670.7 2207.7,2676.58
  pour cut-out: 2464.68,2700.17 2458.36,2700.17 2458.47,2688.06 2479.72,2688.06 2479.72,2693.94
  pour cut-out: 4510.66,2588.93 4504.34,2588.93 4504.45,2576.83 4525.7,2576.83 4525.7,2582.7
  text "2" at 1249.65,6.63 h65
  text ".Layer_Name" at 445.07,-990.08 h60
L3 SIGNAL 1:
  region net 12XX_1_1V0_RF2_FILT: 2618.04,3256.29 2668.29,3256.29 2670.56,3254.02 2670.56,3226.92 2665.38,3221.74 2638.48,3221.74 2633.14,3227.07 2633.14,3239.54 2631.24,3241.45 2618.47,3241.45 2613.33,3246.59 2613.33,3251.44
  region net SYSTEM_5V0: 2515.39,514.41 2579.92,514.41 2585.03,509.31 2585.03,461.62 2579.6,456.18 2512.89,456.18 2507.35,461.73 2507.35,508.77 2513,514.41 2515.32,514.41
  region net 12XX_1_1V8_FILT: 2509.9,3360.96 2509.9,3384.51 2515.63,3390.24 2515.63,3402.55 2526.45,3413.37 2526.45,3418.78 2532.18,3424.51 2537.8,3424.51 2543.21,3419.1 2543.21,3410.19 2535.36,3402.34 2535.36,3398.41 2526.77,3389.82 2526.77,3375.28 2525.18,3373.69 2525.18,3361.59 2519.87,3356.29
  region net 12XX_1_1V0_RF1_FILT: 2242.48,3438.84 2253.42,3427.91 2253.42,3403.17 2258.55,3398.04 2285.85,3398.04 2291.36,3403.54 2291.36,3430.62 2286.08,3435.9 2264.2,3435.9 2260.58,3439.52 2260.58,3446.84 2255.3,3452.12 2247.64,3452.12 2242.48,3446.96
  region net 12XX_1_1V0_RF1_FILT: 1146.34,1308.09 1152.4,1302.04 1179.47,1302.04 1186.13,1308.64 1186.13,1374.29 1180.2,1380.21 1151.78,1380.21 1146.34,1374.77
  region net SYSTEM_1V8: 307.86,2641.07 307.86,2690.07 313.3,2695.51 341.72,2695.51 347.65,2689.59 347.65,2641.78 341.72,2635.86 313.06,2635.86 307.87,2641.06
  region net GND: 2389.91,4689.37 2384.62,4684.08 2384.9,4683.8 2384.9,4635.9 2391.08,4629.72 2437.22,4629.72 2443.65,4636.15 2443.65,4684.1 2438.39,4689.37
  region net SYSTEM_5V0: 2503.12,4689.87 2497.84,4684.58 2498.12,4684.3 2498.12,4636.39 2504.3,4630.22 2550.43,4630.22 2556.87,4636.65 2556.87,4684.6 2551.6,4689.87
  region net GND: 4298.52,4628.49 4304,4623 4304,4575.03 4297.81,4568.84 4232.2,4568.84 4225.74,4575.3 4225.74,4623.2 4231.02,4628.49
  region net SYSTEM_5V0: 4128.16,4421 4122.87,4415.71 4123.16,4415.43 4123.16,4367.52 4129.33,4361.35 4175.47,4361.35 4181.9,4367.78 4181.9,4415.73 4176.64,4421
  region net 12XX_2_1V0_RF1_FILT: 4785.96,3522.44 4780.54,3527.86 4732.59,3527.86 4727.22,3522.56 4727.22,3493.62 4732.48,3488.36 4780.96,3488.36 4786.25,3493.64 4785.96,3493.93
  region net 12XX_2_1V0_RF2_FILT: 5238.93,2890.61 5244.61,2884.92 5272.41,2884.92 5278.44,2890.95 5278.44,2957.75 5273.13,2963.12 5244.19,2963.12 5238.93,2957.86
  region net GND: 5792.46,1199.71 5797.89,1205.13 5797.89,1253.08 5792.58,1258.45 5763.64,1258.45 5758.38,1253.19 5758.38,1204.71 5763.66,1199.43 5763.95,1199.71
  region net 12XX_2_1V0_RF1_FILT: 5530.8,2067.9 5525.52,2062.62 5525.8,2062.33 5525.8,2014.43 5531.98,2008.25 5578.11,2008.25 5584.55,2014.69 5584.55,2062.64 5579.28,2067.9
  region net PMIC2_VIN_B3: 5338.43,1070.07 5333.25,1064.89 5287.55,1064.89 5282.54,1069.9 5282.54,1078.84 5324.94,1121.23 5332.95,1121.23 5338.43,1115.76
  region net PMIC2_VIN_B2: 5570.1,1070.07 5575.28,1064.89 5620.98,1064.89 5625.98,1069.9 5625.98,1078.84 5583.59,1121.23 5575.57,1121.23 5570.1,1115.76
  region net PMIC2_VIN_B0: 5570.1,880.14 5575.28,885.32 5620.98,885.32 5625.98,880.31 5625.98,871.38 5583.59,828.98 5575.57,828.98 5570.1,834.46
  region net PMIC2_VIN_B1: 5338.43,880.14 5333.25,885.32 5287.55,885.32 5282.54,880.31 5282.54,871.38 5324.94,828.98 5332.95,828.98 5338.43,834.46
  region net PMIC1_VIN_B3: 467.7,1857.93 462.53,1852.75 416.83,1852.75 411.82,1857.75 411.82,1866.69 454.22,1909.09 462.23,1909.09 467.7,1903.61
  region net PMIC1_VIN_B2: 699.37,1857.93 704.55,1852.75 750.25,1852.75 755.26,1857.75 755.26,1866.69 712.86,1909.09 704.85,1909.09 699.37,1903.61
  region net PMIC1_VIN_B0: 699.37,1668 704.55,1673.18 750.25,1673.18 755.26,1668.17 755.26,1659.23 712.86,1616.84 704.85,1616.84 699.37,1622.31
  region net PMIC1_VIN_B1: 467.7,1668 462.53,1673.18 416.83,1673.18 411.82,1668.17 411.82,1659.23 454.22,1616.84 462.23,1616.84 467.7,1622.31
  region net GND: 358.22,1523.9 361.4,1523.9 367.2,1518.09 367.2,1490.43 361.79,1485.02 334.16,1485.02 328.59,1490.59 328.59,1518.17 334.32,1523.91 357.48,1523.91
  region net GND: 829.54,1523.9 832.72,1523.9 838.53,1518.09 838.53,1490.43 833.11,1485.02 805.49,1485.02 799.92,1490.59 799.92,1518.17 805.65,1523.91 828.81,1523.91
  region net GND: 829.54,2041.06 832.72,2041.06 838.53,2035.26 838.53,2007.6 833.11,2002.19 805.49,2002.19 799.92,2007.76 799.92,2035.34 805.65,2041.07 828.81,2041.07
  region net GND: 358.22,2041.06 361.4,2041.06 367.2,2035.26 367.2,2007.6 361.79,2002.19 334.16,2002.19 328.59,2007.76 328.59,2035.34 334.32,2041.07 357.48,2041.07
  region net GND: 5228.94,736.04 5232.12,736.04 5237.92,730.24 5237.92,702.58 5232.51,697.17 5204.88,697.17 5199.32,702.74 5199.32,730.32 5205.05,736.05 5228.2,736.05
  region net GND: 5700.27,736.04 5703.45,736.04 5709.25,730.24 5709.25,702.58 5703.84,697.17 5676.21,697.17 5670.64,702.74 5670.64,730.32 5676.38,736.05 5699.53,736.05
  region net GND: 5700.27,1253.21 5703.45,1253.21 5709.25,1247.4 5709.25,1219.74 5703.84,1214.33 5676.21,1214.33 5670.64,1219.9 5670.64,1247.49 5676.38,1253.22 5699.53,1253.22
  region net GND: 5228.94,1253.21 5232.12,1253.21 5237.92,1247.4 5237.92,1219.74 5232.51,1214.33 5204.88,1214.33 5199.32,1219.9 5199.32,1247.49 5205.05,1253.22 5228.2,1253.22
  region net GND: 5793,749.48 5798.42,744.06 5846.37,744.06 5851.74,749.36 5851.74,778.3 5846.48,783.56 5798,783.56 5792.71,778.28 5793,777.99
  region net 12XX_2_1V0_RF1_FILT: 5805.08,436.36 5799.8,431.08 5800.08,430.8 5800.08,382.89 5806.26,376.72 5852.39,376.72 5858.82,383.15 5858.82,431.1 5853.56,436.36
  region net 12XX_2_1V0_RF2_FILT: 5774.35,579.38 5769.06,574.1 5769.34,573.81 5769.34,525.91 5775.52,519.73 5821.66,519.73 5828.09,526.16 5828.09,574.12 5822.82,579.38
  region net 12XX_1_1V0_RF2_FILT: 2761.15,1302.47 2761.15,1284.2 2767.54,1277.81 2794.49,1277.81 2800.93,1284.25 2800.93,1351 2795.01,1356.92 2766.59,1356.92 2761.14,1351.48 2761.14,1302.48
  region net 12XX_2_1V2_FILT: 4755.72,1315.7 4750.43,1310.42 4750.71,1310.13 4750.71,1262.23 4756.89,1256.05 4803.03,1256.05 4809.46,1262.48 4809.46,1310.44 4804.19,1315.7
  region net 12XX_3_1V8_FILT: 4929.6,1404.03 4924.32,1398.74 4924.6,1398.46 4924.6,1350.56 4930.78,1344.38 4976.91,1344.38 4983.34,1350.81 4983.34,1398.77 4978.08,1404.03
  region net SYSTEM_5V0: 3939.25,650.91 3988.25,650.91 3993.69,645.46 3993.69,617.04 3987.77,611.12 3939.96,611.12 3934.04,617.04 3934.04,645.7 3939.24,650.9
  region net SYSTEM_5V0: 3938.79,510.36 3987.79,510.36 3993.24,504.92 3993.24,476.5 3987.32,470.57 3939.51,470.57 3933.59,476.5 3933.59,505.16 3938.79,510.35
  region net GND: 4119.13,512.68 4123.93,507.89 4123.93,437.77 4118.78,432.62 4050.85,432.62 4043.44,440.03 4043.44,505.72 4050.4,512.68
  region net 12XX_3_1V2_FILT: 3927.84,1110.58 3933.19,1115.94 3982.82,1115.94 3987.48,1111.28 3987.48,1062.72 3981.35,1056.58 3934.18,1056.58 3927.84,1062.92
  region net GND: 2385.84,602.06 2390.64,597.26 2390.64,527.15 2385.49,522 2317.55,522 2310.15,529.4 2310.15,595.1 2317.11,602.06
  region net GND: 5191.77,1156.41 5191.77,1118.51 5235.66,1074.61 5254.42,1074.61 5260.41,1080.6 5260.41,1137.89 5237.16,1161.14 5196.5,1161.14 5191.77,1156.41
  region net GND: 5716.76,1156.41 5716.76,1118.51 5672.86,1074.61 5654.11,1074.61 5648.11,1080.6 5648.11,1137.89 5671.36,1161.14 5712.03,1161.14 5716.75,1156.41
  region net GND: 5191.77,793.81 5191.77,831.71 5235.66,875.6 5254.42,875.6 5260.41,869.61 5260.41,812.33 5237.16,789.07 5196.5,789.07 5191.77,793.8
  region net GND: 5694.62,799.08 5694.63,860.05 5679.07,875.6 5654.11,875.6 5644.92,866.42 5644.92,822.29 5674.44,792.77 5688.3,792.77
  region net GND: 5434.21,1071.1 5441.91,1063.4 5466.2,1063.4 5473.9,1071.1 5473.9,1113.59 5499.23,1138.92 5499.23,1196.56 5511.8,1209.13 5622.3,1209.13 5629.68,1216.51 5629.68,1242.04 5615.72,1256 5290.2,1256 5273.64,1239.45 5273.64,1223.69 5286.61,1210.72 5392.52,1210.72 5408.48,1194.77 5408.48,1137.52 5434.21,1111.79
  region net GND: 5434.21,879.11 5441.91,886.81 5466.2,886.81 5473.9,879.11 5473.9,836.63 5499.23,811.3 5499.23,753.65 5511.8,741.08 5622.3,741.08 5629.68,733.7 5629.68,708.17 5615.72,694.21 5290.2,694.21 5273.64,710.77 5273.64,726.52 5286.61,739.49 5392.52,739.49 5408.48,755.45 5408.48,812.69 5434.21,838.42
  region net GND: 563.48,1666.97 571.18,1674.67 595.48,1674.67 603.18,1666.97 603.18,1624.48 628.51,1599.15 628.51,1541.51 641.07,1528.94 751.58,1528.94 758.96,1521.56 758.96,1496.03 745,1482.07 419.47,1482.07 402.92,1498.62 402.92,1514.38 415.88,1527.34 521.8,1527.34 537.75,1543.3 537.75,1600.55 563.48,1626.28
  region net GND: 563.48,1858.96 571.18,1851.26 595.48,1851.26 603.18,1858.96 603.18,1901.44 628.51,1926.77 628.51,1984.42 641.07,1996.98 751.58,1996.98 758.96,2004.36 758.96,2029.9 745,2043.86 419.47,2043.86 402.92,2027.3 402.92,2011.54 415.88,1998.58 521.8,1998.58 537.75,1982.62 537.75,1925.38 563.48,1899.65
  region net GND: 823.89,1586.94 823.9,1647.9 808.34,1663.46 783.38,1663.46 774.2,1654.27 774.2,1610.14 803.71,1580.62 817.58,1580.62
  region net GND: 321.04,1581.66 321.04,1619.56 364.94,1663.46 383.69,1663.46 389.69,1657.46 389.69,1600.18 366.44,1576.93 325.77,1576.93 321.05,1581.66
  region net GND: 846.03,1944.26 846.03,1906.36 802.14,1862.47 783.38,1862.47 777.39,1868.46 777.39,1925.74 800.64,1948.99 841.3,1948.99 846.03,1944.27
  region net GND: 321.04,1944.26 321.04,1906.36 364.94,1862.47 383.69,1862.47 389.69,1868.46 389.69,1925.74 366.44,1948.99 325.77,1948.99 321.05,1944.27
  pour cut-out: 1317.77,2696.74 1317.77,2690.42 1330.23,2690.42 1330.23,2696.74
  pour cut-out: 2186.34,2682.81 2192.66,2682.81 2192.66,2670.35 2186.34,2670.35
  pour cut-out: 4504.34,2588.93 4510.66,2588.93 4510.66,2576.47 4504.34,2576.47
  pour cut-out: 2464.68,2700.17 2458.36,2700.17 2458.47,2688.06 2479.72,2688.06 2479.72,2693.94
  region net SYSTEM_3V3: 215.58,674.66 215.58,627.6 222.37,620.82 269.86,620.82 274.57,625.52 274.57,676.3 270.08,680.79 221.71,680.79
  text "3" at 1250.07,8.31 h65
  text ".Layer_Name" at 445.07,-990.08 h60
